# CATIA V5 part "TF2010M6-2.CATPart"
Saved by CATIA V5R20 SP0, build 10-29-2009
Part number: TF2010M6-2
Revision: ANY
Definition: UNKNOWN
Nomenclature: TF2010M6-2
Source: Unknown
Bounding box of the stored display mesh (mm): x -4.85 to 4.85, y 0 to 4.45, z -4.85 to 4.85
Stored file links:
  C:\Users\Utente\Desktop\IO LAVORO\3D X SITO CF\CUMSA\3D files RCM\RCM 204810\TF2010M6-2.CATPart
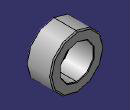
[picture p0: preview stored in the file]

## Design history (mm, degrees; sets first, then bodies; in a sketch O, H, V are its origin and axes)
Body1 "Chaflán2" (main body)
  Solid1: solid without history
